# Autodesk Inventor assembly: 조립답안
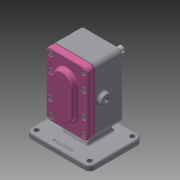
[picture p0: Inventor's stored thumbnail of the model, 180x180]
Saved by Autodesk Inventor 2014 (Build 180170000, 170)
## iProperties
Created: 2020-04
Part Number: 조립답안
Document SubType Name: Assembly
Designer: kh
Author: kh
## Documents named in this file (11)
- C:\Users\kh\Desktop\700407V1022\조립답안.iam
- C:\Users\kh\Desktop\700407V1022\본체IPT.ipt
- C:\Users\kh\Desktop\700407V1022\개스킷.ipt
- C:\Users\kh\Desktop\700407V1022\메인축.ipt
- C:\Users\kh\Desktop\700407V1022\베어링부시.ipt
- C:\Users\kh\Desktop\700407V1022\볼트 M5.ipt
- C:\Users\kh\Desktop\700407V1022\서브축.ipt
- C:\Users\kh\Desktop\700407V1022\스퍼기어.ipt
- C:\Users\kh\Desktop\700407V1022\오일 실 16 28 7.ipt
- C:\Users\kh\Desktop\700407V1022\커버.ipt
- C:\Users\kh\Desktop\700407V1022\키 6 x 6 x 18.ipt
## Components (1 placed, 1 different names)
1. 개스킷:1
